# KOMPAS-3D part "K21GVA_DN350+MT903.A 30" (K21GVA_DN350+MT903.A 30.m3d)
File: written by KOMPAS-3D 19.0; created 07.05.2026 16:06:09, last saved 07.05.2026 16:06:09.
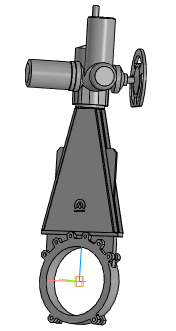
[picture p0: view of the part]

Document properties: Автор: Энергия; Полное имя файла: ..\K21GVA_DN50-DN1000+MT903.A\K21GVA_DN350+MT903.A 30.a3d

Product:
- Part/product: K21GVA_DN350+MT903.A 30
    Масса: 228.591

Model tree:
1. Операция без истории:1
